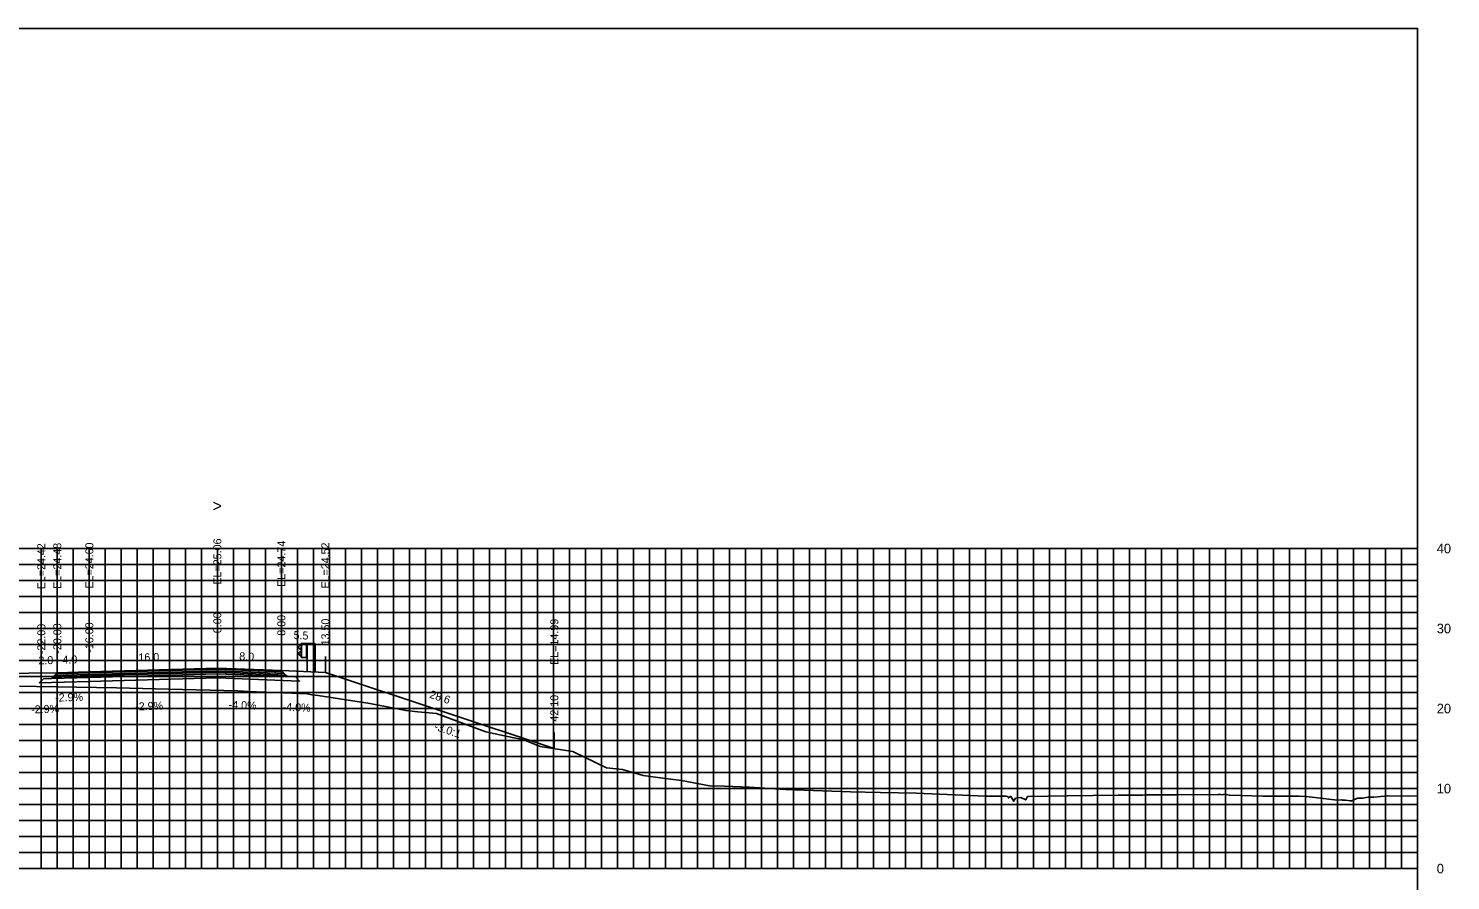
# Model space of a CAD drawing. Extents: x 1797652 to 1804145, y 245981 to 250269.
# Drawn here: x 1803967.4 to 1804145.1, y 250162.9 to 250269.4 of the extents above; entities that cross this region are included whole.
import ezdxf

# ---------------------------------------------------------------- set-up
doc = ezdxf.new("R2010")
doc.units = 0
for name, color, linetype in [('3', 7, 'Continuous'), ('31', 7, 'Continuous'), ('4', 7, 'Continuous'), ('60', 7, 'Continuous'), ('BASE', 7, 'Continuous'), ('CL-CNST', 7, 'Continuous'), ('Level 1', 7, 'Continuous'), ('Level 62', 7, 'Continuous'), ('LOWER BINDER', 7, 'Continuous'), ('M-ROADS', 7, 'Continuous'), ('UPPER BINDER', 7, 'Continuous'), ('WEARING', 7, 'Continuous')]:
    doc.layers.add(name, color=color, linetype=linetype)

msp = doc.modelspace()

# ---------------------------------------------------------------- linework, layer by layer
for p, q in [((1803969, 250188.85), (1803969, 250190.85)), ((1803971, 250188.91), (1803971, 250190.91)), ((1803975, 250189.03), (1803975, 250191.03)), ((1803991, 250189.49), (1803991, 250191.49)), ((1803999, 250189.17), (1803999, 250191.17)), ((1804004.5, 250188.95), (1804004.5, 250190.95)), ((1804033.11, 250179.42), (1804033.11, 250181.42))]:
    msp.add_line(p, q)
msp.add_lwpolyline([(1803841, 250079.43), (1804141, 250079.43), (1804141, 250269.43), (1803841, 250269.43)], close=True)
at = {"layer": '60'}
for p, q in [((1804141, 250164.43), (1804141, 250204.43)), ((1804141.06, 250204.43), (1804141, 250204.43)), ((1804141.06, 250194.43), (1804141, 250194.43)), ((1804141.06, 250184.43), (1804141, 250184.43)), ((1804141.06, 250174.43), (1804141, 250174.43)), ((1803841, 250164.43), (1804141, 250164.43)), ((1803971, 250164.37), (1803971, 250164.43)), ((1803981, 250164.37), (1803981, 250164.43)), ((1803991, 250164.37), (1803991, 250164.43)), ((1804001, 250164.37), (1804001, 250164.43)), ((1804011, 250164.37), (1804011, 250164.43)), ((1804021, 250164.37), (1804021, 250164.43)), ((1804031, 250164.37), (1804031, 250164.43)), ((1804041, 250164.37), (1804041, 250164.43)), ((1804051, 250164.37), (1804051, 250164.43)), ((1804061, 250164.37), (1804061, 250164.43)), ((1804071, 250164.37), (1804071, 250164.43)), ((1804081, 250164.37), (1804081, 250164.43)), ((1804091, 250164.37), (1804091, 250164.43)), ((1804101, 250164.37), (1804101, 250164.43)), ((1804111, 250164.37), (1804111, 250164.43)), ((1804121, 250164.37), (1804121, 250164.43)), ((1804131, 250164.37), (1804131, 250164.43)), ((1804141, 250164.37), (1804141, 250164.43)), ((1804141.06, 250164.43), (1804141, 250164.43))]:
    msp.add_line(p, q, dxfattribs=at)
at = {"layer": 'BASE'}
msp.add_lwpolyline([(1803969.26, 250188.14), (1803970.26, 250188.17), (1803975, 250188.31), (1803991, 250188.77), (1803999.75, 250188.42), (1804000.75, 250188.38), (1804001.27, 250187.86), (1803991, 250188.27), (1803975, 250187.81), (1803968.75, 250187.63)], close=True, dxfattribs=at)
at = {"layer": 'CL-CNST'}
for points in [[(1803964.33, 250188.78), (1803969, 250188.9)], [(1803969, 250188.85), (1803971, 250188.91), (1803975, 250189.03), (1803991, 250189.49), (1803999, 250189.17), (1804004.5, 250188.95), (1804033.11, 250179.42)]]:
    msp.add_lwpolyline(points, dxfattribs=at)
at = {"layer": 'Level 1'}
for p, q in [((1804001.46, 250192.42), (1804001.1, 250192.12)), ((1804001.1, 250192.05), (1804001.46, 250191.76)), ((1804001.46, 250192.57), (1804001.46, 250190.82)), ((1804003.21, 250192.57), (1804001.46, 250192.57)), ((1804001.51, 250192.57), (1804001.51, 250190.82)), ((1804002.16, 250192.57), (1804002.16, 250190.82)), ((1804002.21, 250192.57), (1804002.21, 250189.04)), ((1804003.21, 250192.57), (1804003.21, 250189)), ((1804001.46, 250191.62), (1804001.1, 250191.32)), ((1804001.1, 250191.25), (1804001.46, 250190.97)), ((1804002.21, 250190.82), (1804001.46, 250190.82))]:
    msp.add_line(p, q, dxfattribs=at)
for centre in [(1804001.13, 250192.08), (1804001.13, 250191.29)]:
    msp.add_arc(centre, 0.05, 135, 226.6208, dxfattribs=at)
at = {"layer": 'Level 62'}
for p, q in [((1803841, 250204.43), (1804141, 250204.43)), ((1803969, 250164.43), (1803969, 250204.43)), ((1803971, 250164.43), (1803971, 250204.43)), ((1803973, 250164.43), (1803973, 250204.43)), ((1803975, 250164.43), (1803975, 250204.43)), ((1803977, 250164.43), (1803977, 250204.43)), ((1803979, 250164.43), (1803979, 250204.43)), ((1803981, 250164.43), (1803981, 250204.43)), ((1803983, 250164.43), (1803983, 250204.43)), ((1803985, 250164.43), (1803985, 250204.43)), ((1803987, 250164.43), (1803987, 250204.43)), ((1803989, 250164.43), (1803989, 250204.43)), ((1803991, 250164.43), (1803991, 250204.43)), ((1803993, 250164.43), (1803993, 250204.43)), ((1803995, 250164.43), (1803995, 250204.43)), ((1803997, 250164.43), (1803997, 250204.43)), ((1803999, 250164.43), (1803999, 250204.43)), ((1804001, 250164.43), (1804001, 250204.43)), ((1804003, 250164.43), (1804003, 250204.43)), ((1804005, 250164.43), (1804005, 250204.43)), ((1804007, 250164.43), (1804007, 250204.43)), ((1804009, 250164.43), (1804009, 250204.43)), ((1804011, 250164.43), (1804011, 250204.43)), ((1804013, 250164.43), (1804013, 250204.43)), ((1804015, 250164.43), (1804015, 250204.43)), ((1804017, 250164.43), (1804017, 250204.43)), ((1804019, 250164.43), (1804019, 250204.43)), ((1804021, 250164.43), (1804021, 250204.43)), ((1804023, 250164.43), (1804023, 250204.43)), ((1804025, 250164.43), (1804025, 250204.43)), ((1804027, 250164.43), (1804027, 250204.43)), ((1804029, 250164.43), (1804029, 250204.43)), ((1804031, 250164.43), (1804031, 250204.43)), ((1804033, 250164.43), (1804033, 250204.43)), ((1804035, 250164.43), (1804035, 250204.43)), ((1804037, 250164.43), (1804037, 250204.43)), ((1804039, 250164.43), (1804039, 250204.43)), ((1804041, 250164.43), (1804041, 250204.43)), ((1804043, 250164.43), (1804043, 250204.43)), ((1804045, 250164.43), (1804045, 250204.43)), ((1804047, 250164.43), (1804047, 250204.43)), ((1804049, 250164.43), (1804049, 250204.43)), ((1804051, 250164.43), (1804051, 250204.43)), ((1804053, 250164.43), (1804053, 250204.43)), ((1804055, 250164.43), (1804055, 250204.43)), ((1804057, 250164.43), (1804057, 250204.43)), ((1804059, 250164.43), (1804059, 250204.43)), ((1804061, 250164.43), (1804061, 250204.43)), ((1804063, 250164.43), (1804063, 250204.43)), ((1804065, 250164.43), (1804065, 250204.43)), ((1804067, 250164.43), (1804067, 250204.43)), ((1804069, 250164.43), (1804069, 250204.43)), ((1804071, 250164.43), (1804071, 250204.43)), ((1804073, 250164.43), (1804073, 250204.43)), ((1804075, 250164.43), (1804075, 250204.43)), ((1804077, 250164.43), (1804077, 250204.43)), ((1804079, 250164.43), (1804079, 250204.43)), ((1804081, 250164.43), (1804081, 250204.43)), ((1804083, 250164.43), (1804083, 250204.43)), ((1804085, 250164.43), (1804085, 250204.43)), ((1804087, 250164.43), (1804087, 250204.43)), ((1804089, 250164.43), (1804089, 250204.43)), ((1804091, 250164.43), (1804091, 250204.43)), ((1804093, 250164.43), (1804093, 250204.43)), ((1804095, 250164.43), (1804095, 250204.43)), ((1804097, 250164.43), (1804097, 250204.43)), ((1804099, 250164.43), (1804099, 250204.43)), ((1804101, 250164.43), (1804101, 250204.43)), ((1804103, 250164.43), (1804103, 250204.43)), ((1804105, 250164.43), (1804105, 250204.43)), ((1804107, 250164.43), (1804107, 250204.43)), ((1804109, 250164.43), (1804109, 250204.43)), ((1804111, 250164.43), (1804111, 250204.43)), ((1804113, 250164.43), (1804113, 250204.43)), ((1804115, 250164.43), (1804115, 250204.43)), ((1804117, 250164.43), (1804117, 250204.43)), ((1804119, 250164.43), (1804119, 250204.43)), ((1804121, 250164.43), (1804121, 250204.43)), ((1804123, 250164.43), (1804123, 250204.43)), ((1804125, 250164.43), (1804125, 250204.43)), ((1804127, 250164.43), (1804127, 250204.43)), ((1804129, 250164.43), (1804129, 250204.43)), ((1804131, 250164.43), (1804131, 250204.43)), ((1804133, 250164.43), (1804133, 250204.43)), ((1804135, 250164.43), (1804135, 250204.43)), ((1804137, 250164.43), (1804137, 250204.43)), ((1804139, 250164.43), (1804139, 250204.43)), ((1804141, 250164.43), (1804141, 250204.43)), ((1803841, 250202.43), (1804141, 250202.43)), ((1803841, 250200.43), (1804141, 250200.43)), ((1803841, 250198.43), (1804141, 250198.43)), ((1803841, 250196.43), (1804141, 250196.43)), ((1803841, 250194.43), (1804141, 250194.43)), ((1803841, 250192.43), (1804141, 250192.43)), ((1803841, 250190.43), (1804141, 250190.43)), ((1803841, 250188.43), (1804141, 250188.43)), ((1803841, 250186.43), (1804141, 250186.43)), ((1803841, 250184.43), (1804141, 250184.43)), ((1803841, 250182.43), (1804141, 250182.43)), ((1803841, 250180.43), (1804141, 250180.43)), ((1803841, 250178.43), (1804141, 250178.43)), ((1803841, 250176.43), (1804141, 250176.43)), ((1803841, 250174.43), (1804141, 250174.43)), ((1803841, 250172.43), (1804141, 250172.43)), ((1803841, 250170.43), (1804141, 250170.43)), ((1803841, 250168.43), (1804141, 250168.43)), ((1803841, 250166.43), (1804141, 250166.43)), ((1803841, 250164.43), (1804141, 250164.43))]:
    msp.add_line(p, q, dxfattribs=at)
at = {"layer": 'LOWER BINDER'}
for points in [[(1803975, 250188.5), (1803991, 250188.96), (1803999.55, 250188.62), (1803999.75, 250188.42), (1803991, 250188.77), (1803975, 250188.31), (1803970.26, 250188.17), (1803970.46, 250188.37)], [(1803975, 250188.69), (1803991, 250189.15), (1803999.36, 250188.82), (1803999.55, 250188.62), (1803991, 250188.96), (1803975, 250188.5), (1803970.46, 250188.37), (1803970.65, 250188.56)]]:
    msp.add_lwpolyline(points, close=True, dxfattribs=at)
at = {"layer": 'M-ROADS'}
msp.add_lwpolyline([(1803966.28, 250187.21), (1803968.4, 250187.18), (1803978.38, 250187.03), (1803984.91, 250186.87), (1803993.57, 250186.64), (1803994.25, 250186.6), (1803994.82, 250186.57), (1804000.3, 250186.34), (1804002.21, 250186.26), (1804002.83, 250186.14), (1804003.6, 250186.05), (1804007.36, 250185.46), (1804009.02, 250185.22), (1804010.05, 250185.07), (1804014.58, 250184.17), (1804016.04, 250184.03), (1804018.41, 250183.81), (1804024.55, 250181.51), (1804028.07, 250180.79), (1804029.21, 250180.55), (1804031.36, 250179.67), (1804032.15, 250179.55), (1804035.43, 250179.08), (1804039.64, 250177.01), (1804041.64, 250176.81), (1804044.22, 250176.05), (1804046.68, 250175.72), (1804049.02, 250175.42), (1804052.51, 250174.79), (1804054.38, 250174.72), (1804057.48, 250174.59), (1804062, 250174.33), (1804070.15, 250174.02), (1804073.82, 250173.92), (1804073.85, 250173.92), (1804073.89, 250173.92), (1804078.37, 250173.86), (1804087.06, 250173.48), (1804089.22, 250173.46), (1804089.44, 250173.46), (1804089.58, 250173.48), (1804089.78, 250173.45), (1804089.87, 250173.26), (1804090.1, 250173.44), (1804090.17, 250173.43), (1804090.47, 250172.98), (1804090.51, 250172.82), (1804090.59, 250172.99), (1804090.77, 250173.22), (1804091.43, 250173.32), (1804092.03, 250173.01), (1804092.27, 250173.43), (1804092.34, 250173.44), (1804097.25, 250173.53), (1804103.59, 250173.6), (1804106.65, 250173.62), (1804107.1, 250173.63), (1804107.34, 250173.63), (1804110.37, 250173.66), (1804110.82, 250173.66), (1804116.04, 250173.7), (1804116.36, 250173.68), (1804116.7, 250173.64), (1804116.8, 250173.73), (1804117.1, 250173.7), (1804117.49, 250173.6), (1804121.68, 250173.5), (1804121.93, 250173.49), (1804122.05, 250173.48), (1804122.55, 250173.49), (1804124.43, 250173.49), (1804126.19, 250173.49), (1804127.13, 250173.44), (1804130.95, 250173), (1804131.49, 250173.02), (1804131.52, 250173.04), (1804131.68, 250173), (1804132.01, 250172.99), (1804132.59, 250172.91), (1804132.7, 250172.88), (1804132.77, 250172.87), (1804132.78, 250172.91), (1804133.51, 250173.21), (1804134.13, 250173.22), (1804134.84, 250173.34), (1804135.52, 250173.34), (1804137.27, 250173.51), (1804139.92, 250173.48), (1804141, 250173.51)], dxfattribs=at)
at = {"layer": 'UPPER BINDER'}
msp.add_lwpolyline([(1803999.36, 250188.82), (1803999.16, 250189.02), (1803991, 250189.34), (1803975, 250188.88), (1803970.85, 250188.76), (1803970.65, 250188.56), (1803975, 250188.69), (1803991, 250189.15)], close=True, dxfattribs=at)
at = {"layer": 'WEARING'}
msp.add_lwpolyline([(1803999.16, 250189.02), (1803999, 250189.17), (1803991, 250189.49), (1803975, 250189.03), (1803971, 250188.91), (1803970.85, 250188.76), (1803975, 250188.88), (1803991, 250189.34)], close=True, dxfattribs=at)

# ---------------------------------------------------------------- texts
msp.add_text('-3.0:1', height=1, rotation=341.5652).set_placement((1804018.01, 250181.81))
at = {"layer": '3'}
for s, p in [('EL=24.42', (1803969.5, 250199.33)), ('EL=24.48', (1803971.5, 250199.38)), ('EL=24.60', (1803975.5, 250199.42)), ('EL=25.06', (1803991.5, 250199.92)), ('EL=24.74', (1803999.5, 250199.64)), ('EL=24.52', (1804005, 250199.42)), ('0.00', (1803991.5, 250193.85)), ('8.00', (1803999.5, 250193.53)), ('13.50', (1804005, 250192.32)), ('EL=14.99', (1804033.61, 250189.89)), ('-22.00', (1803969.5, 250191.23)), ('-20.00', (1803971.5, 250191.29)), ('-16.00', (1803975.5, 250191.41)), ('42.10', (1804033.61, 250182.79))]:
    msp.add_text(s, height=1, rotation=90, dxfattribs=at).set_placement(p)
at = {"layer": '31'}
for s, p in [('40', (1804143.4, 250203.83)), ('30', (1804143.4, 250193.83)), ('20', (1804143.4, 250183.83)), ('10', (1804143.4, 250173.83)), ('0', (1804143.4, 250163.83))]:
    msp.add_text(s, height=1.2, dxfattribs=at).set_placement(p)
at = {"layer": '4'}
for s, rotation, p in [('5.5', 357.7094, (1804000.51, 250193.12)), ('2.0', 1.6611, (1803968.65, 250189.94)), ('4.0', 1.6611, (1803971.65, 250190.03)), ('16.0', 1.6611, (1803981.15, 250190.31)), ('8.0', 357.7094, (1803993.72, 250190.48)), ('28.6', 341.5652, (1804017.44, 250185.8)), ('-2.9%', 1.6611, (1803967.74, 250183.82)), ('-2.9%', 1.6611, (1803970.74, 250185.29)), ('-2.9%', 1.6611, (1803980.74, 250184.19)), ('-4.0%', 357.7094, (1803992.39, 250184.43)), ('-4.0%', 357.7094, (1803999.14, 250184.16))]:
    msp.add_text(s, height=1, rotation=rotation, dxfattribs=at).set_placement(p)
at = {"layer": '60'}
msp.add_text('>', height=1.5, dxfattribs=at).set_placement((1803990.39, 250209.03))

doc.saveas('drawing.dxf')
